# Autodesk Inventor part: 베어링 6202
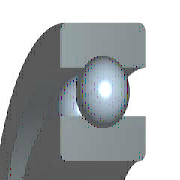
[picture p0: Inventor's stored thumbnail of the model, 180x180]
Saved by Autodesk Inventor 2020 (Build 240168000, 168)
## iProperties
Created: 2012-02
Part Number: 베어링 6202
Material: 강철, 연강
Description: 깊은 그루브 볼 베어링
Document SubType Name: Modeling
Standard: KS B 2023
Designer: mduedu
Standards Organization: KS
Language: ko-KR
Size Designation: 6202 - 15 x 35 x 11
Categories: <MemberInstance><Categories><Category DisplayName="샤프트 부품" InternalName="7f7aeb1f-a693-4053-b835-cee3144e0d98" Mnemonic="SHFT"><Category DisplayName="베어링" Inter
Density: 1 g/cm^3
Appearance: 노란색
IsCustomPart: 1
Author: mduedu
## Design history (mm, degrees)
sketch "스케치" dims "d0" = 5.2 (= -0.26 x WD + 0.26 x BD)
  geometry: L1 (2.9, 12.5)-(8.1, 12.5); L2 (5.5, 12.5)-(5.5, 9.9); L3 (5.5, 12.5)-(5.5, 15.1); L4 (3.568, 10.76)-(0, 10.76); L5 (0, 7.5)-(11, 7.5); L6 (3.568, 14.24)-(0, 14.24); L7 (0, 17.5)-(11, 17.5); L8 (11, 7.5)-(11, 10.76); L9 (7.432, 10.76)-(11, 10.76); L10 (7.432, 14.24)-(11, 14.24); L11 (11, 17.5)-(11, 14.24); L12 (-1.4, 0)-(8.4, 0) reference; L13 (0, -0.3)-(0, 5.3) reference
  constraints: 22 end point, 4 point on line, 2 collinear, 2 perpendicular, 2 symmetric about line, 1 midpoint, 1 parallel, 14 other
  dimensions: "d9" = 15 diameter of L5 L12 (= WD); "d11" = 35 diameter of L7 L12 (= BD); "d12" = 11 distance between parallel lines of L8 L13 (= KB); "d13" = 21.52 diameter of L9 L12 (= 0.326 x BD + 0.674 x WD)
revolve "본체" stored, may be unused: angle "d6" = 90 deg
revolve "볼" stored, may be unused: angle "d7" = 90 deg
pattern_circular "IDS_ARRAYBALL[SIMPL:T]" dims angle "d3" = 360 deg
body "Solid1"
fillet "모깎기1" dims "d1" = 0.6 (= KRS)
other parameters: "WD" = 15 [user parameter; used in 5 equation terms], "BD" = 35 [user parameter; used in 5 equation terms], "KB" = 11 [user parameter; used in 1 equation term], "KRS" = 0.6 [user parameter; used in 1 equation term], "d4" = 0, "d5" = 0, "d8" = 0, "d14" = 0, "d15" = 0, "BBA" = 0 [user parameter], "BC0" = 3750000 [user parameter], "BC" = 7800000 [user parameter], "BR" = 17.5 (= 0.5 x BD) [user parameter], "WR" = 7.5 (= 0.5 x WD) [user parameter]
